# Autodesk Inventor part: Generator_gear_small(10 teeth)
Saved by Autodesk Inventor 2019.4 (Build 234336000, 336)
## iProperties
Created: 2020-02
Part Number: Generator_gear_small(10 teeth)
Material: Generic
Description: Spur Gear; Module: 0.900000; Num Teeth: 10; Pressure Angle: 20.000000; Backlash: 0.00 mm
Document SubType Name: Modeling
Designer: Administrator
Density: 1 g/cm^3
Appearance: Default
Title: Generator_gear_small(10 teeth) v2
Author: Administrator
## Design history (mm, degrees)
feature "Body1"
body "Solid1"
